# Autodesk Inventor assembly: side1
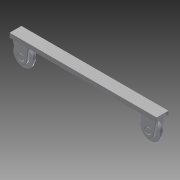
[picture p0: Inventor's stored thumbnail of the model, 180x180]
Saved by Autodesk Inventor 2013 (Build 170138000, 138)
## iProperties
Created: 2009-11
Part Number: side1
Document SubType Name: Assembly
Designer: pokornp
Mass: 81675.3 g
Surface Area: 27453 cm^2
Volume: 26478.2 cm^3
Density: 3.08462 g/cm^3
_SolveAssemblyDoc: Frame Generator Solve Assembly
_Version: 15.0.0
Author: pokornp
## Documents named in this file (6)
- C:\Users\boganb\Documents\B2 Design\Goodyear\2013 Tutorial Files\Frame Analysis 1\side1.iam
- C:\Users\boganb\Documents\B2 Design\Goodyear\2013 Tutorial Files\Frame Analysis 1\Part3.ipt
- C:\Users\boganb\Documents\B2 Design\Goodyear\2013 Tutorial Files\Frame Analysis 1\side1\Frame\Frame0001.iam
- C:\Users\boganb\Documents\B2 Design\Goodyear\2013 Tutorial Files\Frame Analysis 1\shape.ipt
- C:\Users\boganb\Documents\B2 Design\Goodyear\2013 Tutorial Files\Frame Analysis 1\wheel.ipt
- C:\Users\boganb\Documents\B2 Design\Goodyear\2013 Tutorial Files\Frame Analysis 1\axis1.ipt
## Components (8 placed, 5 different names)
1. Part3:1
2. Frame0001:1 [sub-assembly] — Mate:7, Flush:3, Mate:9, Flush:4, Mate:10, Mate:11
3. shape:1 — Mate:1, Flush:1, Mate:3, Mate:9, Flush:4, Mate:10
4. shape:2 — Mate:4, Flush:2, Mate:6, Mate:7, Flush:3, Mate:11
5. wheel:1 — Mate:2, Mate:3
6. wheel:2 — Mate:5, Mate:6
7. axis1:1 — Mate:1, Flush:1, Mate:2
8. axis1:2 — Mate:4, Flush:2, Mate:5
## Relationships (14: Mate 10, Flush 4)
- Mate:1: shape:1 ↔ axis1:1
- Flush:1: shape:1 ↔ axis1:1
- Mate:2: wheel:1 ↔ axis1:1
- Mate:3: shape:1 ↔ wheel:1
- Mate:4: shape:2 ↔ axis1:2
- Flush:2: shape:2 ↔ axis1:2
- Mate:5: wheel:2 ↔ axis1:2
- Mate:6: shape:2 ↔ wheel:2
- Mate:7: Frame0001:1 ↔ shape:2
- Flush:3: Frame0001:1 ↔ shape:2
- Mate:9: Frame0001:1 ↔ shape:1
- Flush:4: Frame0001:1 ↔ shape:1
- Mate:10: Frame0001:1 ↔ shape:1
- Mate:11: Frame0001:1 ↔ shape:2
